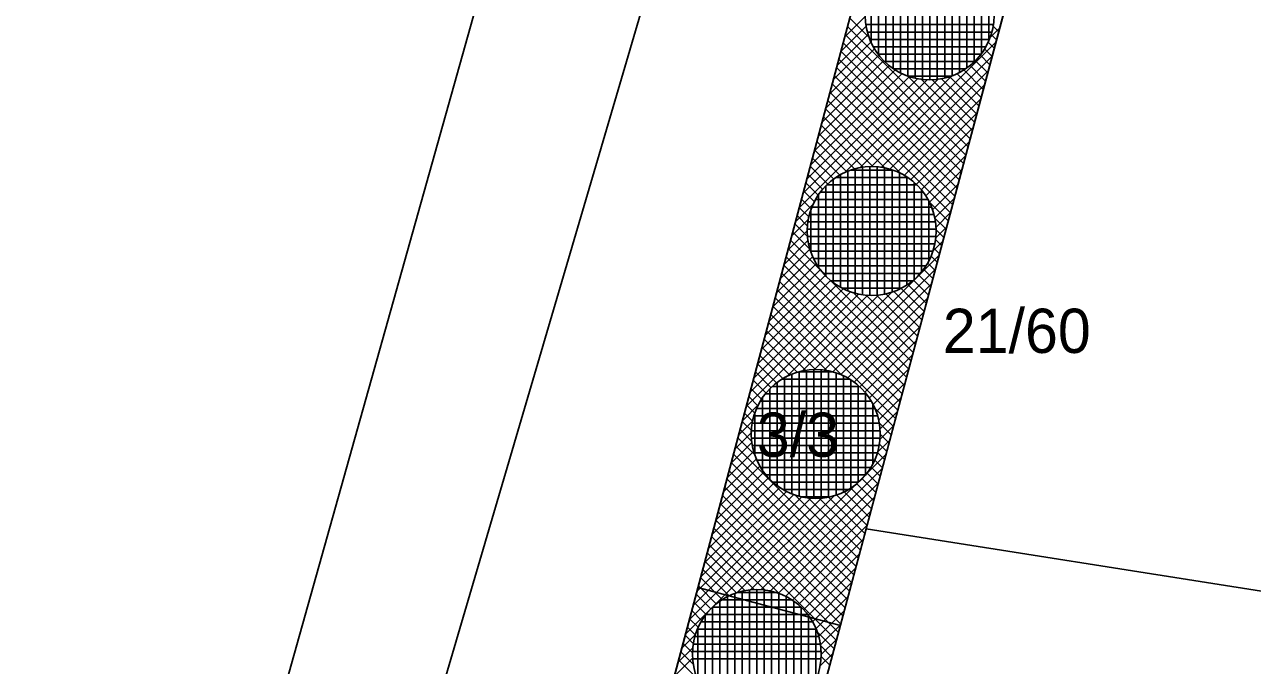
# Model space of a CAD drawing. Extents: x -566461 to -565198, y -1096301 to -1095707.
# Drawn here: x -565860.88 to -565827.55, y -1096067.69 to -1096050.3 of the extents above; entities that cross this region are included whole.
import ezdxf

# ---------------------------------------------------------------- set-up
doc = ezdxf.new("R2010")
doc.units = 0
for name, color, linetype in [('Vrstva 1', 7, 'Continuous'), ('Vrstva 40', 7, 'Continuous'), ('Vrstva 41', 7, 'Continuous'), ('Vrstva 42', 7, 'Continuous'), ('Vrstva 44', 7, 'Continuous')]:
    doc.layers.add(name, color=color, linetype=linetype)

msp = doc.modelspace()

# ---------------------------------------------------------------- linework, layer by layer
at = {"layer": 'Vrstva 1'}
for p, q in [((-565836.72, -1096024.67), (-565860.88, -1096106.94)), ((-565832.07, -1096026.09), (-565854, -1096108.33)), ((-565838.03, -1096063.98), (-565828.2, -1096027.12)), ((-565860.59, -1096092.38), (-565843.23, -1096030.62)), ((-565849.04, -1096105.26), (-565838.03, -1096063.98)), ((-565838.03, -1096063.98), (-565736.97, -1096079.98))]:
    msp.add_line(p, q, dxfattribs=at)
at = {"layer": 'Vrstva 41'}
for p, q in [((-565838.616, -1096050.64), (-565838.049, -1096050.072)), ((-565838.479, -1096050.125), (-565837.933, -1096050.671)), ((-565838.719, -1096051.025), (-565838.025, -1096050.331)), ((-565838.539, -1096050.348), (-565835.267, -1096053.619)), ((-565834.686, -1096050.669), (-565834.406, -1096050.389)), ((-565834.599, -1096050.328), (-565834.434, -1096050.493)), ((-565838.925, -1096051.797), (-565837.895, -1096050.767)), ((-565838.822, -1096051.411), (-565837.972, -1096050.561)), ((-565838.658, -1096050.795), (-565835.387, -1096054.066)), ((-565838.598, -1096050.571), (-565835.327, -1096053.843)), ((-565837.893, -1096054.159), (-565834.509, -1096050.775)), ((-565834.725, -1096050.768), (-565834.553, -1096050.94)), ((-565834.648, -1096050.562), (-565834.493, -1096050.717)), ((-565839.131, -1096052.568), (-565837.681, -1096051.118)), ((-565839.028, -1096052.183), (-565837.797, -1096050.951)), ((-565838.717, -1096051.018), (-565835.446, -1096054.289)), ((-565837.629, -1096054.178), (-565834.612, -1096051.16)), ((-565834.939, -1096051.119), (-565834.672, -1096051.387)), ((-565834.824, -1096050.952), (-565834.612, -1096051.163)), ((-565839.336, -1096053.34), (-565837.4, -1096051.403)), ((-565839.234, -1096052.954), (-565837.548, -1096051.269)), ((-565838.836, -1096051.465), (-565835.565, -1096054.736)), ((-565838.777, -1096051.241), (-565835.506, -1096054.513)), ((-565835.22, -1096051.404), (-565834.791, -1096051.833)), ((-565835.072, -1096051.269), (-565834.731, -1096051.61)), ((-565839.851, -1096055.268), (-565836.37, -1096051.787)), ((-565839.748, -1096054.882), (-565836.625, -1096051.76)), ((-565839.645, -1096054.497), (-565836.852, -1096051.704)), ((-565839.542, -1096054.111), (-565837.053, -1096051.622)), ((-565839.439, -1096053.725), (-565837.235, -1096051.521)), ((-565838.896, -1096051.688), (-565835.625, -1096054.959)), ((-565838.627, -1096054.328), (-565836.072, -1096051.772)), ((-565838.207, -1096054.19), (-565835.691, -1096051.674)), ((-565837.397, -1096054.228), (-565834.714, -1096051.546)), ((-565836.931, -1096051.673), (-565835.208, -1096053.396)), ((-565836.549, -1096051.772), (-565835.148, -1096053.173)), ((-565836.251, -1096051.787), (-565835.089, -1096052.95)), ((-565835.996, -1096051.76), (-565835.029, -1096052.726)), ((-565835.769, -1096051.704), (-565834.97, -1096052.503)), ((-565835.567, -1096051.622), (-565834.91, -1096052.28)), ((-565835.385, -1096051.522), (-565834.851, -1096052.056)), ((-565839.015, -1096052.135), (-565835.744, -1096055.406)), ((-565838.955, -1096051.911), (-565835.684, -1096055.182)), ((-565837.187, -1096054.302), (-565834.817, -1096051.932)), ((-565839.075, -1096052.358), (-565837.075, -1096054.357)), ((-565837, -1096054.397), (-565834.92, -1096052.318)), ((-565839.194, -1096052.804), (-565837.838, -1096054.16)), ((-565839.134, -1096052.581), (-565837.52, -1096054.196)), ((-565836.83, -1096054.511), (-565835.023, -1096052.703)), ((-565839.253, -1096053.028), (-565838.107, -1096054.174)), ((-565836.678, -1096054.641), (-565835.126, -1096053.089)), ((-565839.372, -1096053.474), (-565838.553, -1096054.294)), ((-565839.313, -1096053.251), (-565838.341, -1096054.223)), ((-565836.542, -1096054.788), (-565835.229, -1096053.475)), ((-565839.432, -1096053.698), (-565838.743, -1096054.387)), ((-565839.551, -1096054.144), (-565839.068, -1096054.627)), ((-565839.491, -1096053.921), (-565838.914, -1096054.498)), ((-565836.422, -1096054.951), (-565835.332, -1096053.86)), ((-565839.61, -1096054.368), (-565839.206, -1096054.772)), ((-565836.319, -1096055.131), (-565835.435, -1096054.246)), ((-565839.73, -1096054.814), (-565839.432, -1096055.112)), ((-565839.67, -1096054.591), (-565839.327, -1096054.934)), ((-565836.235, -1096055.33), (-565835.537, -1096054.632)), ((-565839.953, -1096055.654), (-565839.452, -1096055.153)), ((-565839.789, -1096055.037), (-565839.517, -1096055.309)), ((-565836.337, -1096055.095), (-565835.803, -1096055.629)), ((-565836.174, -1096055.551), (-565835.64, -1096055.018)), ((-565839.908, -1096055.484), (-565839.616, -1096055.776)), ((-565839.849, -1096055.261), (-565839.581, -1096055.528)), ((-565836.143, -1096055.803), (-565835.743, -1096055.403)), ((-565840.056, -1096056.039), (-565839.59, -1096055.573)), ((-565839.968, -1096055.707), (-565839.614, -1096056.061)), ((-565836.176, -1096055.54), (-565835.863, -1096055.852)), ((-565836.159, -1096056.102), (-565835.846, -1096055.789)), ((-565840.262, -1096056.811), (-565839.602, -1096056.151)), ((-565840.159, -1096056.425), (-565839.621, -1096055.887)), ((-565840.087, -1096056.154), (-565839.176, -1096057.065)), ((-565840.027, -1096055.931), (-565839.543, -1096056.415)), ((-565836.23, -1096056.455), (-565835.949, -1096056.175)), ((-565836.161, -1096056.12), (-565835.982, -1096056.299)), ((-565836.14, -1096055.858), (-565835.922, -1096056.076)), ((-565840.365, -1096057.197), (-565839.552, -1096056.383)), ((-565840.146, -1096056.377), (-565836.875, -1096059.648)), ((-565836.203, -1096056.361), (-565836.042, -1096056.522)), ((-565840.571, -1096057.968), (-565839.383, -1096056.78)), ((-565840.468, -1096057.582), (-565839.478, -1096056.593)), ((-565840.265, -1096056.824), (-565836.994, -1096060.095)), ((-565840.206, -1096056.601), (-565836.935, -1096059.872)), ((-565839.178, -1096059.686), (-565836.052, -1096056.56)), ((-565836.367, -1096056.763), (-565836.161, -1096056.969)), ((-565836.274, -1096056.573), (-565836.101, -1096056.745)), ((-565840.776, -1096058.739), (-565839.139, -1096057.102)), ((-565840.673, -1096058.354), (-565839.269, -1096056.95)), ((-565840.325, -1096057.047), (-565837.054, -1096060.318)), ((-565838.942, -1096059.734), (-565836.155, -1096056.946)), ((-565836.607, -1096057.088), (-565836.28, -1096057.415)), ((-565836.478, -1096056.934), (-565836.22, -1096057.192)), ((-565841.085, -1096059.896), (-565838.649, -1096057.461)), ((-565840.982, -1096059.511), (-565838.829, -1096057.358)), ((-565840.879, -1096059.125), (-565838.992, -1096057.238)), ((-565840.444, -1096057.494), (-565837.173, -1096060.765)), ((-565840.385, -1096057.27), (-565837.114, -1096060.541)), ((-565839.045, -1096057.196), (-565836.816, -1096059.425)), ((-565838.731, -1096059.806), (-565836.258, -1096057.332)), ((-565837.092, -1096057.452), (-565836.458, -1096058.085)), ((-565836.914, -1096057.347), (-565836.399, -1096057.862)), ((-565836.752, -1096057.226), (-565836.339, -1096057.639)), ((-565841.29, -1096060.668), (-565838.229, -1096057.606)), ((-565841.188, -1096060.282), (-565838.45, -1096057.545)), ((-565840.504, -1096057.717), (-565837.233, -1096060.988)), ((-565840.215, -1096059.875), (-565837.977, -1096057.637)), ((-565839.766, -1096059.709), (-565837.688, -1096057.631)), ((-565839.447, -1096059.673), (-565837.325, -1096057.55)), ((-565838.54, -1096059.898), (-565836.36, -1096057.718)), ((-565838.395, -1096057.563), (-565836.756, -1096059.202)), ((-565838.041, -1096057.634), (-565836.697, -1096058.978)), ((-565837.756, -1096057.636), (-565836.637, -1096058.755)), ((-565837.508, -1096057.601), (-565836.578, -1096058.532)), ((-565837.289, -1096057.537), (-565836.518, -1096058.309)), ((-565840.623, -1096058.164), (-565839.086, -1096059.701)), ((-565840.563, -1096057.94), (-565838.673, -1096059.831)), ((-565838.369, -1096060.009), (-565836.463, -1096058.103)), ((-565840.682, -1096058.387), (-565839.399, -1096059.67)), ((-565838.215, -1096060.138), (-565836.566, -1096058.489)), ((-565840.801, -1096058.834), (-565839.892, -1096059.743)), ((-565840.742, -1096058.61), (-565839.66, -1096059.692)), ((-565840.861, -1096059.057), (-565840.1, -1096059.818)), ((-565838.077, -1096060.283), (-565836.669, -1096058.875)), ((-565840.98, -1096059.503), (-565840.455, -1096060.028)), ((-565840.92, -1096059.28), (-565840.287, -1096059.914)), ((-565837.955, -1096060.444), (-565836.772, -1096059.26)), ((-565841.04, -1096059.727), (-565840.607, -1096060.16)), ((-565837.851, -1096060.623), (-565836.875, -1096059.646)), ((-565841.159, -1096060.173), (-565840.862, -1096060.47)), ((-565841.099, -1096059.95), (-565840.742, -1096060.307)), ((-565837.765, -1096060.82), (-565836.978, -1096060.032)), ((-565841.218, -1096060.397), (-565840.963, -1096060.651)), ((-565837.701, -1096061.038), (-565837.08, -1096060.418)), ((-565841.393, -1096061.053), (-565840.935, -1096060.595)), ((-565841.337, -1096060.843), (-565841.106, -1096061.074)), ((-565841.278, -1096060.62), (-565841.047, -1096060.851)), ((-565837.821, -1096060.683), (-565837.292, -1096061.211)), ((-565837.667, -1096061.287), (-565837.183, -1096060.803)), ((-565841.496, -1096061.439), (-565841.101, -1096061.044)), ((-565841.397, -1096061.067), (-565841.135, -1096061.328)), ((-565837.691, -1096061.096), (-565837.352, -1096061.435)), ((-565841.599, -1096061.825), (-565841.137, -1096061.363)), ((-565841.516, -1096061.513), (-565841.039, -1096061.99)), ((-565841.456, -1096061.29), (-565841.126, -1096061.621)), ((-565837.678, -1096061.581), (-565837.286, -1096061.189)), ((-565837.66, -1096061.409), (-565837.411, -1096061.658)), ((-565841.702, -1096062.211), (-565841.124, -1096061.632)), ((-565841.575, -1096061.736), (-565838.305, -1096065.007)), ((-565837.739, -1096061.924), (-565837.389, -1096061.575)), ((-565837.687, -1096061.665), (-565837.471, -1096061.881)), ((-565841.908, -1096062.982), (-565841.004, -1096062.079)), ((-565841.805, -1096062.596), (-565841.076, -1096061.868)), ((-565841.635, -1096061.96), (-565838.364, -1096065.231)), ((-565841.179, -1096065.648), (-565837.492, -1096061.96)), ((-565837.808, -1096062.11), (-565837.59, -1096062.328)), ((-565837.733, -1096061.902), (-565837.53, -1096062.104)), ((-565842.113, -1096063.753), (-565840.801, -1096062.441)), ((-565842.01, -1096063.368), (-565840.912, -1096062.27)), ((-565841.754, -1096062.406), (-565838.483, -1096065.677)), ((-565841.695, -1096062.183), (-565838.424, -1096065.454)), ((-565840.893, -1096065.644), (-565837.595, -1096062.346)), ((-565838.018, -1096062.465), (-565837.709, -1096062.774)), ((-565837.904, -1096062.297), (-565837.649, -1096062.551)), ((-565842.319, -1096064.525), (-565840.527, -1096062.733)), ((-565842.216, -1096064.139), (-565840.672, -1096062.595)), ((-565841.814, -1096062.63), (-565838.543, -1096065.9)), ((-565840.642, -1096065.676), (-565837.698, -1096062.732)), ((-565838.297, -1096062.752), (-565837.828, -1096063.221)), ((-565838.15, -1096062.617), (-565837.769, -1096062.998)), ((-565842.936, -1096066.839), (-565839.238, -1096063.141)), ((-565842.833, -1096066.453), (-565839.523, -1096063.143)), ((-565842.73, -1096066.067), (-565839.772, -1096063.109)), ((-565842.627, -1096065.682), (-565839.99, -1096063.045)), ((-565842.525, -1096065.296), (-565840.187, -1096062.959)), ((-565842.422, -1096064.91), (-565840.366, -1096062.855)), ((-565841.933, -1096063.076), (-565838.662, -1096066.347)), ((-565841.873, -1096062.853), (-565838.602, -1096066.124)), ((-565841.539, -1096065.724), (-565838.886, -1096063.071)), ((-565840.422, -1096065.739), (-565837.801, -1096063.118)), ((-565839.98, -1096063.049), (-565838.245, -1096064.784)), ((-565839.611, -1096063.136), (-565838.185, -1096064.561)), ((-565839.318, -1096063.145), (-565838.126, -1096064.337)), ((-565839.064, -1096063.116), (-565838.066, -1096064.114)), ((-565838.841, -1096063.057), (-565838.007, -1096063.891)), ((-565838.641, -1096062.973), (-565837.947, -1096063.668)), ((-565838.46, -1096062.872), (-565837.888, -1096063.444)), ((-565841.992, -1096063.299), (-565838.721, -1096066.57)), ((-565840.224, -1096065.824), (-565837.903, -1096063.503)), ((-565842.111, -1096063.746), (-565838.841, -1096067.017)), ((-565842.052, -1096063.523), (-565838.781, -1096066.794)), ((-565842.171, -1096063.969), (-565840.388, -1096065.752)), ((-565840.044, -1096065.927), (-565838.006, -1096063.889)), ((-565842.29, -1096064.416), (-565841.064, -1096065.642)), ((-565842.23, -1096064.193), (-565840.767, -1096065.656)), ((-565839.882, -1096066.048), (-565838.109, -1096064.275)), ((-565842.349, -1096064.639), (-565841.319, -1096065.67)), ((-565839.736, -1096066.185), (-565838.212, -1096064.66)), ((-565842.469, -1096065.086), (-565841.746, -1096065.808)), ((-565842.409, -1096064.863), (-565841.545, -1096065.727)), ((-565839.606, -1096066.337), (-565838.315, -1096065.046)), ((-565842.528, -1096065.309), (-565841.928, -1096065.909)), ((-565839.493, -1096066.507), (-565838.418, -1096065.432)), ((-565842.647, -1096065.756), (-565842.241, -1096066.162)), ((-565842.588, -1096065.532), (-565842.093, -1096066.027)), ((-565839.4, -1096066.697), (-565838.521, -1096065.818)), ((-565842.707, -1096065.979), (-565842.373, -1096066.312)), ((-565842.826, -1096066.426), (-565842.587, -1096066.664)), ((-565842.766, -1096066.202), (-565842.489, -1096066.48)), ((-565839.327, -1096066.907), (-565838.624, -1096066.203)), ((-565843.039, -1096067.224), (-565842.656, -1096066.841)), ((-565842.885, -1096066.649), (-565842.664, -1096066.871)), ((-565839.372, -1096066.768), (-565838.9, -1096067.24)), ((-565839.277, -1096067.14), (-565838.726, -1096066.589)), ((-565843.004, -1096067.096), (-565842.74, -1096067.36)), ((-565842.945, -1096066.872), (-565842.716, -1096067.101)), ((-565839.276, -1096067.147), (-565838.96, -1096067.463)), ((-565839.262, -1096067.407), (-565838.829, -1096066.975)), ((-565843.245, -1096067.996), (-565842.736, -1096067.487)), ((-565843.142, -1096067.61), (-565842.732, -1096067.201)), ((-565843.064, -1096067.319), (-565842.715, -1096067.668)), ((-565839.295, -1096067.723), (-565838.932, -1096067.36)), ((-565839.265, -1096067.441), (-565839.019, -1096067.687)), ((-565843.124, -1096067.542), (-565842.599, -1096068.067))]:
    msp.add_line(p, q, dxfattribs=at)
at = {"layer": 'Vrstva 42'}
msp.add_line((-565838.732, -1096066.611), (-565842.6, -1096065.579), dxfattribs=at)
msp.add_lwpolyline([(-565828.2, -1096027.12), (-565826.72, -1096023.51), (-565829.55, -1096025.32), (-565832.07, -1096026.09), (-565854, -1096108.33), (-565697.28, -1096140.23), (-565696.05, -1096136.4), (-565849.04, -1096105.26)], close=True, dxfattribs=at)
at = {"layer": 'Vrstva 44'}
for p, q in [((-565837.1, -1096051.611), (-565837.1, -1096048.489)), ((-565836.9, -1096051.696), (-565836.9, -1096048.404)), ((-565836.7, -1096051.756), (-565836.7, -1096048.346)), ((-565836.5, -1096051.789), (-565836.5, -1096048.312)), ((-565836.3, -1096051.798), (-565836.3, -1096048.301)), ((-565836.1, -1096051.785), (-565836.1, -1096048.313)), ((-565835.9, -1096051.75), (-565835.9, -1096048.351)), ((-565835.7, -1096051.69), (-565835.7, -1096048.412)), ((-565835.5, -1096051.599), (-565835.5, -1096048.5)), ((-565837.5, -1096051.332), (-565837.5, -1096048.767)), ((-565837.3, -1096051.491), (-565837.3, -1096048.609)), ((-565835.3, -1096051.477), (-565835.3, -1096048.623)), ((-565835.1, -1096051.312), (-565835.1, -1096048.787)), ((-565837.7, -1096051.11), (-565837.7, -1096048.989)), ((-565834.9, -1096051.085), (-565834.9, -1096049.016)), ((-565837.9, -1096050.78), (-565837.9, -1096049.32)), ((-565834.7, -1096050.731), (-565834.7, -1096049.366)), ((-565834.579, -1096050.3), (-565838.042, -1096050.3)), ((-565834.619, -1096050.5), (-565837.999, -1096050.5)), ((-565834.687, -1096050.7), (-565837.933, -1096050.7)), ((-565834.783, -1096050.9), (-565837.839, -1096050.9)), ((-565834.91, -1096051.1), (-565837.708, -1096051.1)), ((-565835.088, -1096051.3), (-565837.534, -1096051.3)), ((-565835.334, -1096051.5), (-565837.287, -1096051.5)), ((-565835.73, -1096051.7), (-565836.887, -1096051.7)), ((-565838.13, -1096057.631), (-565838.13, -1096054.17)), ((-565837.93, -1096057.649), (-565837.93, -1096054.153)), ((-565837.73, -1096057.642), (-565837.73, -1096054.158)), ((-565838.93, -1096057.298), (-565838.93, -1096054.501)), ((-565836.901, -1096054.45), (-565838.857, -1096054.45)), ((-565838.73, -1096057.428), (-565838.73, -1096054.373)), ((-565838.53, -1096057.525), (-565838.53, -1096054.276)), ((-565837.303, -1096054.25), (-565838.458, -1096054.25)), ((-565838.33, -1096057.59), (-565838.33, -1096054.21)), ((-565837.53, -1096057.613), (-565837.53, -1096054.186)), ((-565837.33, -1096057.559), (-565837.33, -1096054.24)), ((-565837.13, -1096057.481), (-565837.13, -1096054.321)), ((-565836.93, -1096057.368), (-565836.93, -1096054.431)), ((-565839.13, -1096057.122), (-565839.13, -1096054.678)), ((-565836.656, -1096054.65), (-565839.103, -1096054.65)), ((-565836.73, -1096057.217), (-565836.73, -1096054.583)), ((-565836.53, -1096057.01), (-565836.53, -1096054.787)), ((-565836.351, -1096055.05), (-565839.408, -1096055.05)), ((-565839.33, -1096056.877), (-565839.33, -1096054.924)), ((-565836.482, -1096054.85), (-565839.279, -1096054.85)), ((-565836.33, -1096056.709), (-565836.33, -1096055.091)), ((-565836.191, -1096055.45), (-565839.57, -1096055.45)), ((-565839.53, -1096056.481), (-565839.53, -1096055.317)), ((-565836.257, -1096055.25), (-565839.503, -1096055.25)), ((-565836.149, -1096055.65), (-565839.611, -1096055.65)), ((-565836.131, -1096055.85), (-565839.628, -1096055.85)), ((-565836.138, -1096056.05), (-565839.622, -1096056.05)), ((-565836.167, -1096056.25), (-565839.593, -1096056.25)), ((-565836.221, -1096056.45), (-565839.541, -1096056.45)), ((-565836.3, -1096056.65), (-565839.46, -1096056.65)), ((-565836.412, -1096056.85), (-565839.347, -1096056.85)), ((-565836.563, -1096057.05), (-565839.198, -1096057.05)), ((-565836.77, -1096057.25), (-565838.992, -1096057.25)), ((-565837.071, -1096057.45), (-565838.692, -1096057.45)), ((-565840.05, -1096063.035), (-565840.05, -1096059.786)), ((-565838.953, -1096059.72), (-565839.851, -1096059.72)), ((-565839.85, -1096063.1), (-565839.85, -1096059.72)), ((-565839.65, -1096063.141), (-565839.65, -1096059.68)), ((-565839.45, -1096063.159), (-565839.45, -1096059.663)), ((-565839.25, -1096063.152), (-565839.25, -1096059.668)), ((-565839.05, -1096063.123), (-565839.05, -1096059.696)), ((-565838.85, -1096063.069), (-565838.85, -1096059.75)), ((-565838.65, -1096062.991), (-565838.65, -1096059.831)), ((-565838.22, -1096060.12), (-565840.581, -1096060.12)), ((-565840.45, -1096062.808), (-565840.45, -1096060.011)), ((-565838.486, -1096059.92), (-565840.317, -1096059.92)), ((-565840.25, -1096062.938), (-565840.25, -1096059.883)), ((-565838.45, -1096062.878), (-565838.45, -1096059.941)), ((-565838.25, -1096062.727), (-565838.25, -1096060.093)), ((-565840.85, -1096062.387), (-565840.85, -1096060.434)), ((-565838.033, -1096060.32), (-565840.767, -1096060.32)), ((-565840.65, -1096062.632), (-565840.65, -1096060.188)), ((-565838.05, -1096062.52), (-565838.05, -1096060.297)), ((-565841.05, -1096061.991), (-565841.05, -1096060.827)), ((-565837.792, -1096060.72), (-565841.006, -1096060.72)), ((-565837.895, -1096060.52), (-565840.907, -1096060.52)), ((-565837.85, -1096062.219), (-565837.85, -1096060.601)), ((-565837.676, -1096061.12), (-565841.125, -1096061.12)), ((-565837.722, -1096060.92), (-565841.078, -1096060.92)), ((-565837.654, -1096061.32), (-565841.147, -1096061.32)), ((-565837.654, -1096061.52), (-565841.145, -1096061.52)), ((-565837.679, -1096061.72), (-565841.12, -1096061.72)), ((-565837.728, -1096061.92), (-565841.072, -1096061.92)), ((-565837.802, -1096062.12), (-565840.999, -1096062.12)), ((-565837.905, -1096062.32), (-565840.893, -1096062.32)), ((-565838.05, -1096062.52), (-565840.751, -1096062.52)), ((-565838.241, -1096062.72), (-565840.557, -1096062.72)), ((-565838.518, -1096062.92), (-565840.281, -1096062.92)), ((-565839.037, -1096063.12), (-565839.77, -1096063.12)), ((-565841.8, -1096068.936), (-565841.8, -1096065.824)), ((-565841.6, -1096069.022), (-565841.6, -1096065.737)), ((-565840.478, -1096065.71), (-565841.518, -1096065.71)), ((-565841.4, -1096069.083), (-565841.4, -1096065.678)), ((-565841.2, -1096069.118), (-565841.2, -1096065.643)), ((-565841, -1096069.128), (-565841, -1096065.631)), ((-565840.8, -1096069.117), (-565840.8, -1096065.642)), ((-565840.6, -1096069.082), (-565840.6, -1096065.678)), ((-565840.4, -1096069.024), (-565840.4, -1096065.738)), ((-565840.2, -1096068.935), (-565840.2, -1096065.825)), ((-565839.798, -1096066.11), (-565842.203, -1096066.11)), ((-565842.2, -1096068.653), (-565842.2, -1096066.107)), ((-565842, -1096068.814), (-565842, -1096065.946)), ((-565840.052, -1096065.91), (-565841.948, -1096065.91)), ((-565840, -1096068.814), (-565840, -1096065.946)), ((-565839.8, -1096068.652), (-565839.8, -1096066.108)), ((-565839.483, -1096066.51), (-565842.517, -1096066.51)), ((-565842.4, -1096068.427), (-565842.4, -1096066.332)), ((-565839.618, -1096066.31), (-565842.383, -1096066.31)), ((-565839.6, -1096068.43), (-565839.6, -1096066.333)), ((-565839.385, -1096066.71), (-565842.615, -1096066.71)), ((-565842.6, -1096068.088), (-565842.6, -1096066.675)), ((-565839.4, -1096068.084), (-565839.4, -1096066.672)), ((-565839.273, -1096067.11), (-565842.729, -1096067.11)), ((-565839.316, -1096066.91), (-565842.684, -1096066.91)), ((-565839.252, -1096067.31), (-565842.748, -1096067.31)), ((-565839.255, -1096067.51), (-565842.743, -1096067.51))]:
    msp.add_line(p, q, dxfattribs=at)
for centre in [(-565836.31, -1096050.05), (-565837.88, -1096055.9), (-565839.4, -1096061.41), (-565841, -1096067.38)]:
    msp.add_circle(centre, 1.75, dxfattribs=at)

# ---------------------------------------------------------------- texts
at = {"layer": 'Vrstva 40'}
for s, p in [('21/60', (-565835.95, -1096059.21)), ('3/3', (-565841, -1096062.03))]:
    msp.add_text(s, height=1.2, dxfattribs=at).set_placement(p)

doc.saveas('drawing.dxf')
